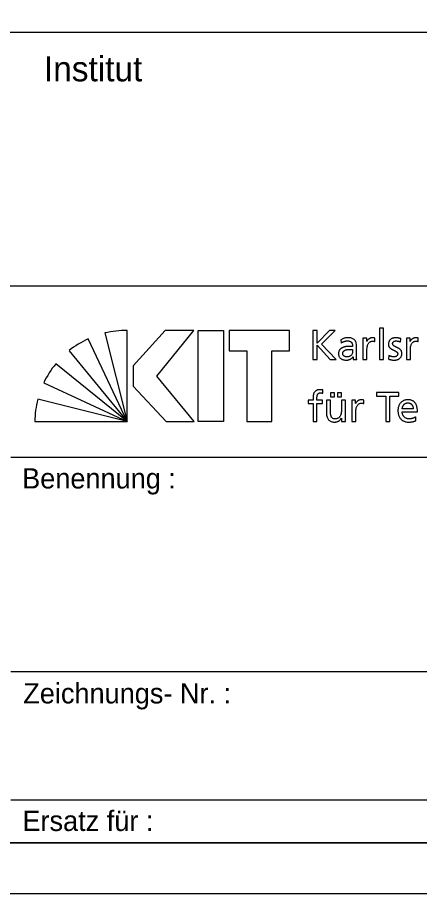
# Model space of a CAD drawing. Extents: x 0 to 168, y 0 to 119.
# Drawn here: x 150.53 to 158.47, y 0 to 17.3 of the extents above; entities that cross this region are included whole.
import ezdxf

# ---------------------------------------------------------------- set-up
doc = ezdxf.new("R2010")
doc.units = 0
doc.layers.add('90_Plankopf', color=7, linetype='Continuous')

msp = doc.modelspace()

# ---------------------------------------------------------------- linework, layer by layer
at = {"layer": '90_Plankopf'}
for p, q in [((167.2, 16.998), (131.624, 16.998)), ((131.624, 11.998), (167.2, 11.998)), ((131.624, 11.998), (167.2, 11.998)), ((152.696, 9.317), (152.696, 11.117)), ((156.362, 11.117), (156.362, 10.541)), ((152.696, 9.317), (151.927, 10.95)), ((152.255, 11.067), (152.696, 9.317)), ((156.916, 10.932), (156.92, 10.866)), ((157.585, 10.897), (157.585, 10.966)), ((158.091, 10.888), (158.098, 10.956)), ((158.442, 10.897), (158.442, 10.966)), ((157.146, 10.742), (157.146, 10.705)), ((157.224, 10.624), (157.224, 10.798)), ((151.549, 10.717), (152.696, 9.317)), ((157.859, 10.624), (157.855, 10.554)), ((152.696, 9.317), (151.287, 10.457)), ((156.362, 10.541), (156.444, 10.541)), ((156.701, 10.541), (156.822, 10.541)), ((151.048, 10.083), (152.696, 9.317)), ((156.555, 9.879), (156.558, 9.941)), ((152.696, 9.317), (150.932, 9.758)), ((157.365, 9.673), (157.365, 9.742)), ((158.341, 9.568), (158.123, 9.568)), ((158.123, 9.51), (158.424, 9.51)), ((158.392, 9.335), (158.392, 9.412)), ((150.873, 9.317), (152.696, 9.317)), ((150.4, 8.614), (167.2, 8.614)), ((150.4, 4.384), (167.2, 4.384)), ((150.4, 1.846), (167.2, 1.846)), ((167.2, 1), (131.624, 1)), ((133.96, 1), (167.2, 1)), ((133.96, 1), (167.2, 1))]:
    msp.add_line(p, q, dxfattribs=at)
for points in [[(0, 0), (168.2, 0), (168.2, 118.8), (0, 118.8)], [(5, 117.8), (167.2, 117.8), (167.2, 1), (5, 1)], [(154.013, 11.117), (153.447, 11.117), (152.815, 10.42), (152.815, 10.018), (153.468, 9.317), (154.017, 9.317), (153.284, 10.213)], [(154.594, 11.117), (154.594, 9.317), (154.1, 9.317), (154.1, 11.117)], [(154.712, 11.117), (154.712, 10.712), (155.06, 10.712), (155.06, 9.317), (155.554, 9.317), (155.554, 10.712), (155.902, 10.712), (155.902, 11.117)]]:
    msp.add_lwpolyline(points, close=True, dxfattribs=at)
for points in [[(156.822, 10.541), (156.529, 10.845), (156.8, 11.117), (156.69, 11.117), (156.444, 10.864), (156.444, 11.117), (156.362, 11.117)], [(157.676, 10.541), (157.754, 10.541), (157.754, 11.16), (157.676, 11.16), (157.676, 10.541)], [(157.424, 10.897), (157.423, 10.897), (157.423, 10.962), (157.35, 10.962), (157.35, 10.541), (157.428, 10.541), (157.428, 10.733)], [(158.281, 10.897), (158.28, 10.897), (158.28, 10.962), (158.207, 10.962), (158.207, 10.541), (158.285, 10.541), (158.285, 10.733)], [(156.444, 10.541), (156.444, 10.823), (156.701, 10.541)], [(157.153, 10.596), (157.154, 10.596), (157.154, 10.541), (157.227, 10.541)], [(156.711, 9.885), (156.711, 9.803), (156.788, 9.803), (156.788, 9.885), (156.711, 9.885)], [(156.846, 9.885), (156.846, 9.803), (156.924, 9.803), (156.924, 9.885), (156.846, 9.885)], [(157.798, 9.317), (157.881, 9.317), (157.881, 9.821), (158.06, 9.821), (158.06, 9.893), (157.619, 9.893), (157.619, 9.821), (157.798, 9.821), (157.798, 9.317)], [(156.365, 9.777), (156.365, 9.738), (156.266, 9.738), (156.266, 9.676), (156.365, 9.676), (156.365, 9.317), (156.442, 9.317), (156.442, 9.676), (156.554, 9.676), (156.554, 9.738), (156.442, 9.738), (156.442, 9.784)], [(156.708, 9.52), (156.708, 9.738), (156.631, 9.738), (156.631, 9.488)], [(157.003, 9.317), (157.003, 9.738), (156.925, 9.738), (156.925, 9.543)], [(157.204, 9.673), (157.203, 9.673), (157.203, 9.738), (157.13, 9.738), (157.13, 9.317), (157.208, 9.317), (157.208, 9.509)], [(156.926, 9.384), (156.928, 9.384), (156.928, 9.317), (157.003, 9.317)]]:
    msp.add_lwpolyline(points, dxfattribs=at)
for centre, start, end in [((152.69, 9.211), 89.8053, 103.1895), ((152.732, 9.224), 115.0126, 128.3968), ((152.763, 9.253), 140.7898, 154.174), ((152.778, 9.288), 165.7222, 179.1064)]:
    msp.add_arc(centre, 1.906, start, end, dxfattribs=at)
for points in [[(157.224, 10.798), (157.224, 10.836), (157.218, 10.868), (157.207, 10.894), (157.195, 10.92), (157.177, 10.939), (157.152, 10.952), (157.127, 10.965), (157.094, 10.972), (157.054, 10.972), (157.028, 10.972), (157.003, 10.968), (156.98, 10.961), (156.956, 10.954), (156.935, 10.944), (156.916, 10.932)], [(156.92, 10.866), (156.931, 10.875), (156.943, 10.883), (156.956, 10.889), (156.969, 10.896), (156.983, 10.901), (156.998, 10.904), (157.013, 10.908), (157.027, 10.909), (157.042, 10.909), (157.068, 10.909), (157.088, 10.905), (157.104, 10.897), (157.119, 10.889), (157.13, 10.877), (157.136, 10.86), (157.143, 10.844), (157.146, 10.824), (157.146, 10.799)], [(157.585, 10.966), (157.58, 10.967), (157.575, 10.968), (157.57, 10.969), (157.565, 10.97), (157.56, 10.971), (157.554, 10.971), (157.548, 10.972), (157.542, 10.972), (157.534, 10.972), (157.519, 10.972), (157.505, 10.969), (157.49, 10.962), (157.476, 10.956), (157.464, 10.947), (157.452, 10.936), (157.441, 10.925), (157.431, 10.912), (157.424, 10.897)], [(157.428, 10.733), (157.428, 10.768), (157.433, 10.799), (157.442, 10.824), (157.451, 10.85), (157.465, 10.87), (157.482, 10.883), (157.499, 10.897), (157.519, 10.904), (157.542, 10.904), (157.549, 10.904), (157.556, 10.904), (157.564, 10.903), (157.571, 10.902), (157.578, 10.9), (157.585, 10.897)], [(158.098, 10.956), (158.083, 10.96), (158.067, 10.964), (158.052, 10.967), (158.036, 10.97), (158.019, 10.972), (158.001, 10.972), (157.981, 10.972), (157.961, 10.969), (157.943, 10.964), (157.925, 10.959), (157.909, 10.951), (157.896, 10.94), (157.882, 10.929), (157.872, 10.916), (157.864, 10.9), (157.857, 10.883), (157.853, 10.864), (157.853, 10.842), (157.853, 10.826), (157.856, 10.811), (157.863, 10.799), (157.869, 10.787), (157.878, 10.776), (157.889, 10.767), (157.9, 10.758), (157.912, 10.75), (157.925, 10.743), (157.938, 10.736), (157.951, 10.729), (157.963, 10.723), (157.976, 10.717), (157.988, 10.711), (157.999, 10.704), (158.01, 10.698), (158.019, 10.691), (158.025, 10.683), (158.032, 10.675), (158.035, 10.665), (158.035, 10.654), (158.035, 10.643), (158.033, 10.633), (158.028, 10.626), (158.023, 10.618), (158.017, 10.612), (158.009, 10.607), (158.001, 10.602), (157.993, 10.599), (157.983, 10.597), (157.974, 10.595), (157.965, 10.594), (157.956, 10.594), (157.948, 10.594), (157.939, 10.595), (157.928, 10.597), (157.917, 10.599), (157.905, 10.603), (157.893, 10.607), (157.881, 10.612), (157.87, 10.617), (157.859, 10.624)], [(157.855, 10.554), (157.873, 10.545), (157.892, 10.539), (157.912, 10.536), (157.931, 10.532), (157.951, 10.531), (157.971, 10.531), (157.99, 10.531), (158.008, 10.534), (158.025, 10.539), (158.043, 10.544), (158.059, 10.552), (158.073, 10.563), (158.086, 10.574), (158.097, 10.588), (158.105, 10.604), (158.114, 10.621), (158.118, 10.64), (158.118, 10.662), (158.118, 10.682), (158.114, 10.698), (158.108, 10.711), (158.101, 10.724), (158.092, 10.736), (158.082, 10.745), (158.071, 10.754), (158.059, 10.762), (158.046, 10.769), (158.033, 10.776), (158.02, 10.782), (158.007, 10.787), (157.994, 10.793), (157.982, 10.799), (157.972, 10.805), (157.961, 10.812), (157.952, 10.819), (157.945, 10.827), (157.939, 10.836), (157.936, 10.846), (157.935, 10.858), (157.936, 10.87), (157.939, 10.879), (157.946, 10.887), (157.953, 10.894), (157.962, 10.9), (157.973, 10.904), (157.984, 10.908), (157.996, 10.909), (158.01, 10.909), (158.014, 10.909), (158.02, 10.909), (158.028, 10.908), (158.035, 10.906), (158.043, 10.905), (158.051, 10.903), (158.059, 10.901), (158.067, 10.898), (158.074, 10.896), (158.081, 10.893), (158.087, 10.891), (158.091, 10.888)], [(158.442, 10.966), (158.437, 10.967), (158.432, 10.968), (158.427, 10.969), (158.422, 10.97), (158.417, 10.971), (158.411, 10.971), (158.405, 10.972), (158.399, 10.972), (158.391, 10.972), (158.376, 10.972), (158.362, 10.969), (158.347, 10.962), (158.333, 10.956), (158.321, 10.947), (158.309, 10.936), (158.298, 10.925), (158.288, 10.912), (158.281, 10.897)], [(158.285, 10.733), (158.285, 10.768), (158.29, 10.799), (158.299, 10.824), (158.308, 10.85), (158.322, 10.87), (158.339, 10.883), (158.356, 10.897), (158.376, 10.904), (158.399, 10.904), (158.406, 10.904), (158.413, 10.904), (158.421, 10.903), (158.428, 10.902), (158.435, 10.9), (158.442, 10.897)], [(157.146, 10.799), (157.136, 10.8), (157.127, 10.8), (157.118, 10.801), (157.109, 10.801), (157.1, 10.801), (157.092, 10.801), (157.083, 10.801), (157.074, 10.801), (157.064, 10.801), (157.047, 10.801), (157.03, 10.8), (157.013, 10.797), (156.995, 10.794), (156.977, 10.789), (156.96, 10.783), (156.943, 10.776), (156.928, 10.768), (156.914, 10.757), (156.9, 10.746), (156.889, 10.733), (156.881, 10.718), (156.872, 10.702), (156.868, 10.684), (156.868, 10.662), (156.868, 10.632), (156.875, 10.607), (156.888, 10.588), (156.901, 10.568), (156.919, 10.554), (156.942, 10.545), (156.965, 10.536), (156.992, 10.531), (157.022, 10.531), (157.04, 10.531), (157.056, 10.534), (157.07, 10.538), (157.084, 10.542), (157.097, 10.547), (157.107, 10.554), (157.118, 10.56), (157.127, 10.567), (157.135, 10.575), (157.142, 10.582), (157.148, 10.589), (157.153, 10.596)], [(157.146, 10.705), (157.146, 10.684), (157.142, 10.665), (157.133, 10.648), (157.124, 10.631), (157.111, 10.618), (157.093, 10.609), (157.076, 10.599), (157.054, 10.594), (157.029, 10.594), (157.02, 10.594), (157.011, 10.596), (157.002, 10.598), (156.993, 10.601), (156.984, 10.606), (156.976, 10.611), (156.969, 10.617), (156.962, 10.625), (156.958, 10.633), (156.953, 10.641), (156.951, 10.651), (156.95, 10.662), (156.951, 10.677), (156.954, 10.69), (156.962, 10.699), (156.969, 10.709), (156.978, 10.717), (156.99, 10.723), (157.001, 10.729), (157.014, 10.733), (157.027, 10.736), (157.04, 10.739), (157.053, 10.741), (157.065, 10.742), (157.077, 10.743), (157.088, 10.743), (157.097, 10.743), (157.105, 10.743), (157.113, 10.743), (157.121, 10.743), (157.13, 10.742), (157.138, 10.742), (157.146, 10.742)], [(157.227, 10.541), (157.226, 10.545), (157.226, 10.551), (157.225, 10.557), (157.225, 10.564), (157.224, 10.573), (157.224, 10.584), (157.224, 10.595), (157.224, 10.608), (157.224, 10.624)], [(156.558, 9.941), (156.55, 9.942), (156.542, 9.944), (156.534, 9.945), (156.525, 9.946), (156.516, 9.946), (156.506, 9.946), (156.478, 9.946), (156.454, 9.942), (156.436, 9.934), (156.417, 9.926), (156.403, 9.915), (156.392, 9.9), (156.382, 9.885), (156.375, 9.867), (156.371, 9.847), (156.367, 9.826), (156.365, 9.803), (156.365, 9.777)], [(156.442, 9.784), (156.442, 9.798), (156.443, 9.811), (156.445, 9.823), (156.446, 9.835), (156.45, 9.846), (156.455, 9.855), (156.46, 9.864), (156.468, 9.871), (156.478, 9.876), (156.488, 9.881), (156.501, 9.883), (156.518, 9.883), (156.524, 9.883), (156.531, 9.883), (156.538, 9.882), (156.544, 9.881), (156.55, 9.88), (156.555, 9.879)], [(157.365, 9.742), (157.36, 9.743), (157.355, 9.744), (157.35, 9.745), (157.345, 9.746), (157.34, 9.747), (157.334, 9.747), (157.328, 9.748), (157.322, 9.748), (157.314, 9.748), (157.299, 9.748), (157.285, 9.745), (157.27, 9.738), (157.256, 9.732), (157.244, 9.723), (157.232, 9.712), (157.221, 9.701), (157.211, 9.688), (157.204, 9.673)], [(158.424, 9.51), (158.424, 9.544), (158.421, 9.576), (158.414, 9.605), (158.408, 9.634), (158.398, 9.659), (158.384, 9.68), (158.369, 9.701), (158.35, 9.718), (158.326, 9.73), (158.302, 9.742), (158.273, 9.748), (158.238, 9.748), (158.208, 9.748), (158.181, 9.743), (158.157, 9.732), (158.133, 9.722), (158.112, 9.707), (158.095, 9.688), (158.077, 9.669), (158.064, 9.647), (158.055, 9.621), (158.046, 9.595), (158.041, 9.567), (158.041, 9.535), (158.041, 9.501), (158.045, 9.47), (158.054, 9.442), (158.062, 9.414), (158.076, 9.39), (158.094, 9.37), (158.112, 9.35), (158.134, 9.334), (158.162, 9.324), (158.189, 9.313), (158.221, 9.308), (158.259, 9.307), (158.282, 9.308), (158.301, 9.309), (158.317, 9.312), (158.333, 9.315), (158.347, 9.319), (158.359, 9.323), (158.371, 9.327), (158.382, 9.331), (158.392, 9.335)], [(158.123, 9.568), (158.125, 9.582), (158.128, 9.596), (158.133, 9.609), (158.138, 9.623), (158.144, 9.636), (158.154, 9.647), (158.162, 9.659), (158.174, 9.668), (158.187, 9.675), (158.201, 9.682), (158.217, 9.685), (158.236, 9.685), (158.253, 9.685), (158.268, 9.682), (158.281, 9.676), (158.294, 9.67), (158.305, 9.662), (158.314, 9.651), (158.323, 9.64), (158.33, 9.628), (158.334, 9.614), (158.339, 9.6), (158.341, 9.584), (158.341, 9.568)], [(156.925, 9.543), (156.925, 9.518), (156.923, 9.494), (156.918, 9.473), (156.913, 9.452), (156.905, 9.434), (156.895, 9.418), (156.884, 9.403), (156.871, 9.391), (156.855, 9.383), (156.839, 9.374), (156.819, 9.37), (156.797, 9.37), (156.775, 9.371), (156.757, 9.378), (156.744, 9.389), (156.731, 9.4), (156.722, 9.417), (156.716, 9.439), (156.711, 9.46), (156.708, 9.488), (156.708, 9.52)], [(157.208, 9.509), (157.208, 9.544), (157.213, 9.575), (157.222, 9.6), (157.232, 9.626), (157.245, 9.646), (157.262, 9.659), (157.279, 9.673), (157.299, 9.68), (157.322, 9.68), (157.329, 9.681), (157.336, 9.68), (157.344, 9.679), (157.351, 9.678), (157.358, 9.676), (157.365, 9.673)], [(156.631, 9.488), (156.631, 9.45), (156.636, 9.418), (156.647, 9.391), (156.659, 9.364), (156.676, 9.343), (156.699, 9.329), (156.722, 9.315), (156.752, 9.308), (156.788, 9.307), (156.808, 9.308), (156.827, 9.311), (156.845, 9.317), (156.863, 9.323), (156.879, 9.332), (156.893, 9.343), (156.907, 9.354), (156.918, 9.368), (156.926, 9.384)], [(158.392, 9.412), (158.387, 9.408), (158.38, 9.404), (158.37, 9.399), (158.361, 9.394), (158.351, 9.39), (158.339, 9.385), (158.327, 9.381), (158.314, 9.377), (158.301, 9.374), (158.288, 9.372), (158.275, 9.37), (158.262, 9.37), (158.243, 9.37), (158.226, 9.374), (158.209, 9.38), (158.193, 9.387), (158.178, 9.397), (158.165, 9.409), (158.152, 9.421), (158.142, 9.436), (158.135, 9.453), (158.127, 9.471), (158.123, 9.49), (158.123, 9.51)]]:
    msp.add_open_spline(points, degree=3, dxfattribs=at)

# ---------------------------------------------------------------- texts
for s, height, p in [('Institut', 0.4928, (151.053, 16.035)), ('Benennung :', 0.4, (150.623, 7.996)), ('Zeichnungs- Nr. :', 0.4, (150.645, 3.752)), ('Ersatz für :', 0.4, (150.628, 1.234))]:
    msp.add_text(s, height=height, dxfattribs=at).set_placement(p)

doc.saveas('drawing.dxf')
